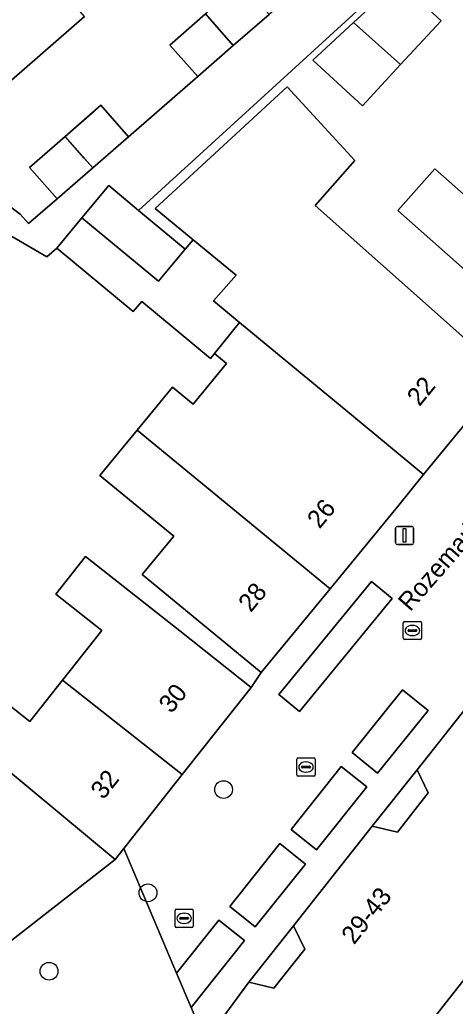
# Model space of a CAD drawing. Extents: x 161881 to 162523, y 381678 to 382381.
# Drawn here: x 162060.4 to 162084.3, y 382033.4 to 382087.6 of the extents above; entities that cross this region are included whole.
import ezdxf

# ---------------------------------------------------------------- set-up
doc = ezdxf.new("R2010")
doc.units = 0
for name, color, linetype in [('IMGEO_Boom', 7, 'Continuous'), ('IMGEO_Erf', 7, 'Continuous'), ('IMGEO_Groenvoorziening', 7, 'Continuous'), ('IMGEO_Kolk', 7, 'Continuous'), ('IMGEO_Lichtmast', 7, 'Continuous'), ('IMGEO_Openbare_ruimte_label', 7, 'Continuous'), ('IMGEO_Pand', 7, 'Continuous'), ('IMGEO_Pand_nummerreeks', 7, 'Continuous'), ('IMGEO_Pand_overbouw', 7, 'Continuous'), ('IMGEO_Pand_vergunning_verleend', 7, 'Continuous'), ('IMGEO_Parkeervlak_open', 7, 'Continuous'), ('IMGEO_Voetpad_open', 7, 'Continuous'), ('IMGEO_Woonerf_open', 7, 'Continuous')]:
    doc.layers.add(name, color=color, linetype=linetype)

msp = doc.modelspace()

# ---------------------------------------------------------------- linework, layer by layer
at = {"layer": 'IMGEO_Boom'}
for centre in [(162071.575, 382045.33), (162067.42, 382039.66), (162061.986, 382035.347)]:
    msp.add_circle(centre, 0.489, dxfattribs=at)
at = {"layer": 'IMGEO_Erf'}
for points in [[(162082.663, 382091.572), (162066.905, 382077.16), (162069.466, 382075.03), (162069.907, 382075.539), (162067.809, 382077.272), (162075.073, 382083.943), (162078.794, 382079.892), (162076.599, 382077.421), (162083.323, 382071.448), (162087.06, 382068.127), (162088.904, 382070.275), (162085.161, 382073.6), (162081.15, 382077.162), (162083.182, 382079.449), (162084.764, 382078.044), (162086.776, 382080.309), (162089.102, 382082.927), (162086.522, 382085.22), (162088.893, 382087.889), (162089.263, 382087.5), (162093.223, 382091.242)], [(162063.941, 382087.819), (162059.914, 382084.317), (162058.933, 382085.442), (162055.177, 382082.169), (162055.093, 382082.095), (162054.473, 382082.858), (162054.137, 382083.272), (162047.556, 382090.818)], [(162046.474, 382089.736), (162054.365, 382081.454), (162060.406, 382076.959), (162060.864, 382076.431), (162062.431, 382077.793), (162060.912, 382079.512), (162062.876, 382081.227), (162064.84, 382082.941), (162066.352, 382081.201), (162070.152, 382084.523), (162068.617, 382086.246), (162070.588, 382087.957)], [(162056.627, 382052.463), (162060.925, 382049.066), (162062.728, 382051.348), (162064.882, 382054.073), (162062.357, 382056.068), (162063.994, 382058.14), (162069.171, 382054.049), (162073.094, 382050.949), (162073.647, 382051.758), (162069.786, 382054.935), (162067.099, 382057.145), (162068.834, 382059.255), (162064.779, 382062.591), (162066.827, 382065.081), (162068.774, 382067.448), (162069.903, 382066.519), (162071.74, 382068.742), (162071.071, 382069.292), (162070.851, 382069.018), (162067.077, 382072.157), (162066.61, 382071.596), (162062.408, 382075.091), (162061.871, 382074.611), (162053.625, 382079.413)]]:
    msp.add_lwpolyline(points, dxfattribs=at)
msp.add_lwpolyline([(162081.303, 382085.172), (162079.207, 382082.908), (162076.484, 382085.416), (162078.71, 382087.476), (162081.182, 382089.764), (162083.536, 382087.585)], close=True, dxfattribs=at)
at = {"layer": 'IMGEO_Groenvoorziening'}
msp.add_lwpolyline([(162075.743, 382049.628), (162080.84, 382055.823), (162079.704, 382056.757), (162074.607, 382050.562)], close=True, dxfattribs=at)
at = {"layer": 'IMGEO_Kolk'}
for p, q in [((162081.447, 382053.644), (162081.447, 382054.496)), ((162081.522, 382054.57), (162082.374, 382054.57)), ((162081.749, 382054.113), (162082.147, 382054.113)), ((162081.935, 382054.35), (162081.96, 382054.35)), ((162082.448, 382054.496), (162082.448, 382053.644)), ((162082.374, 382053.57), (162081.522, 382053.57)), ((162081.706, 382054.064), (162081.706, 382054.076)), ((162082.144, 382054.027), (162081.746, 382054.027)), ((162081.958, 382053.79), (162081.933, 382053.79)), ((162082.19, 382054.076), (162082.19, 382054.064)), ((162075.678, 382047.068), (162076.53, 382047.068)), ((162075.603, 382046.142), (162075.603, 382046.994)), ((162075.862, 382046.562), (162075.862, 382046.574)), ((162076.3, 382046.525), (162075.902, 382046.525)), ((162075.905, 382046.611), (162076.303, 382046.611)), ((162076.091, 382046.848), (162076.116, 382046.848)), ((162076.346, 382046.574), (162076.346, 382046.562)), ((162076.604, 382046.994), (162076.604, 382046.142)), ((162076.53, 382046.068), (162075.678, 382046.068)), ((162076.114, 382046.288), (162076.089, 382046.288)), ((162068.907, 382037.829), (162068.907, 382038.681)), ((162068.982, 382038.755), (162069.834, 382038.755)), ((162069.395, 382038.535), (162069.42, 382038.535)), ((162069.908, 382038.681), (162069.908, 382037.829)), ((162069.166, 382038.249), (162069.166, 382038.261)), ((162069.604, 382038.212), (162069.206, 382038.212)), ((162069.209, 382038.298), (162069.607, 382038.298)), ((162069.418, 382037.975), (162069.393, 382037.975)), ((162069.65, 382038.261), (162069.65, 382038.249)), ((162069.834, 382037.755), (162068.982, 382037.755))]:
    msp.add_line(p, q, dxfattribs=at)
for points in [[(162081.447, 382053.644), (162081.447, 382054.496)], [(162081.522, 382054.57), (162082.374, 382054.57)], [(162082.448, 382054.496), (162082.448, 382053.644)], [(162082.374, 382053.57), (162081.522, 382053.57)], [(162075.678, 382047.068), (162076.53, 382047.068)], [(162075.603, 382046.142), (162075.603, 382046.994)], [(162076.604, 382046.994), (162076.604, 382046.142)], [(162076.53, 382046.068), (162075.678, 382046.068)], [(162068.907, 382037.829), (162068.907, 382038.681)], [(162068.982, 382038.755), (162069.834, 382038.755)], [(162069.908, 382038.681), (162069.908, 382037.829)], [(162069.834, 382037.755), (162068.982, 382037.755)]]:
    msp.add_lwpolyline(points, dxfattribs=at)
for centre, radius, start, end in [((162081.524, 382054.494), 0.0765, 91.552, 178.448), ((162081.524, 382054.494), 0.0765, 91.552, 178.448), ((162081.746, 382054.073), 0.0403, 85.8775, 175.7526), ((162082.151, 382054.075), 0.0386, 1.7309, 96.639), ((162082.372, 382054.494), 0.0765, 1.552, 88.448), ((162082.372, 382054.494), 0.0765, 1.552, 88.448), ((162081.524, 382053.646), 0.0765, 181.552, 268.448), ((162081.524, 382053.646), 0.0765, 181.552, 268.448), ((162081.743, 382054.063), 0.0366, 178.938, 274.7102), ((162082.147, 382054.07), 0.043, 264.8664, 352.4533), ((162082.372, 382053.646), 0.0765, 271.552, 358.448), ((162082.372, 382053.646), 0.0765, 271.552, 358.448), ((162075.68, 382046.992), 0.0765, 91.552, 178.448), ((162075.68, 382046.992), 0.0765, 91.552, 178.448), ((162076.528, 382046.992), 0.0765, 1.552, 88.448), ((162076.528, 382046.992), 0.0765, 1.552, 88.448), ((162075.902, 382046.571), 0.0403, 85.8775, 175.7526), ((162075.899, 382046.561), 0.0366, 178.938, 274.7102), ((162076.303, 382046.568), 0.043, 264.8664, 352.4533), ((162076.307, 382046.573), 0.0386, 1.7309, 96.639), ((162075.68, 382046.144), 0.0765, 181.552, 268.448), ((162075.68, 382046.144), 0.0765, 181.552, 268.448), ((162076.528, 382046.144), 0.0765, 271.552, 358.448), ((162076.528, 382046.144), 0.0765, 271.552, 358.448), ((162068.984, 382038.679), 0.0765, 91.552, 178.448), ((162068.984, 382038.679), 0.0765, 91.552, 178.448), ((162069.832, 382038.679), 0.0765, 1.552, 88.448), ((162069.832, 382038.679), 0.0765, 1.552, 88.448), ((162068.984, 382037.831), 0.0765, 181.552, 268.448), ((162068.984, 382037.831), 0.0765, 181.552, 268.448), ((162069.206, 382038.258), 0.0403, 85.8775, 175.7526), ((162069.203, 382038.248), 0.0366, 178.938, 274.7102), ((162069.607, 382038.255), 0.043, 264.8664, 352.4533), ((162069.611, 382038.26), 0.0386, 1.7309, 96.639), ((162069.832, 382037.831), 0.0765, 271.552, 358.448), ((162069.832, 382037.831), 0.0765, 271.552, 358.448)]:
    msp.add_arc(centre, radius, start, end, dxfattribs=at)
for centre, major_axis, ratio, start_param, end_param in [((162081.934, 382054.07), (-0.387, 0.002), 0.722429, 4.712389, 7.853982), ((162081.959, 382054.07), (-0.39, 0.002), 0.717154, 1.570796, 4.712389), ((162076.09, 382046.568), (-0.387, 0.002), 0.722429, 4.712389, 7.853982), ((162076.115, 382046.568), (-0.39, 0.002), 0.717154, 1.570796, 4.712389), ((162069.394, 382038.255), (-0.387, 0.002), 0.722429, 4.712389, 7.853982), ((162069.419, 382038.255), (-0.39, 0.002), 0.717154, 1.570796, 4.712389)]:
    msp.add_ellipse(centre, major_axis=major_axis, ratio=ratio, start_param=start_param, end_param=end_param, dxfattribs=at)
at = {"layer": 'IMGEO_Lichtmast'}
for p, q in [((162081.023, 382058.897), (162081.023, 382059.697)), ((162081.023, 382059.697), (162081.023, 382058.897)), ((162081.123, 382059.797), (162081.913, 382059.797)), ((162081.913, 382059.797), (162081.123, 382059.797)), ((162082.013, 382059.697), (162082.013, 382058.897)), ((162082.013, 382058.897), (162082.013, 382059.697)), ((162081.913, 382058.797), (162081.123, 382058.797)), ((162081.123, 382058.797), (162081.913, 382058.797))]:
    msp.add_line(p, q, dxfattribs=at)
msp.add_lwpolyline([(162081.443, 382059.672), (162081.593, 382059.672), (162081.593, 382058.922), (162081.443, 382058.922), (162081.443, 382059.672)], dxfattribs=at)
for centre, start, end in [((162081.123, 382059.697), 90, 180), ((162081.123, 382059.697), 90, 180), ((162081.913, 382059.697), 0, 90), ((162081.913, 382059.697), 360, 90), ((162081.123, 382058.897), 180, 270), ((162081.123, 382058.897), 180, 270), ((162081.913, 382058.897), 270, 0), ((162081.913, 382058.897), 270, 0)]:
    msp.add_arc(centre, 0.1, start, end, dxfattribs=at)
at = {"layer": 'IMGEO_Pand'}
for points in [[(162055.4, 382097.641), (162051.36, 382094.127), (162058.933, 382085.442), (162059.914, 382084.317), (162063.941, 382087.819)], [(162072.56, 382089.667), (162070.588, 382087.957), (162072.1, 382086.214), (162074.071, 382087.926)], [(162081.303, 382085.172), (162083.536, 382087.585), (162081.182, 382089.764), (162078.71, 382087.476)], [(162070.588, 382087.957), (162068.617, 382086.246), (162070.152, 382084.523), (162072.1, 382086.214)], [(162081.303, 382085.172), (162078.71, 382087.476), (162076.484, 382085.416), (162079.207, 382082.908)], [(162076.599, 382077.421), (162078.794, 382079.892), (162075.073, 382083.943), (162067.809, 382077.272), (162069.907, 382075.539), (162072.259, 382073.596), (162071.012, 382072.194), (162072.448, 382071.006), (162078.704, 382065.833), (162082.558, 382062.647), (162087.06, 382068.127), (162083.323, 382071.448)], [(162064.84, 382082.941), (162062.876, 382081.227), (162064.388, 382079.494), (162066.352, 382081.201)], [(162064.388, 382079.494), (162062.876, 382081.227), (162060.912, 382079.512), (162062.431, 382077.793)], [(162086.776, 382080.309), (162084.764, 382078.044), (162083.182, 382079.449), (162081.15, 382077.162), (162085.161, 382073.6), (162088.904, 382070.275), (162092.947, 382074.826)], [(162066.905, 382077.16), (162065.264, 382078.525), (162063.784, 382076.746), (162067.999, 382073.266), (162069.466, 382075.03)], [(162063.784, 382076.746), (162062.408, 382075.091), (162066.61, 382071.596), (162067.077, 382072.157), (162070.851, 382069.018), (162071.071, 382069.292), (162072.448, 382071.006), (162071.012, 382072.194), (162072.259, 382073.596), (162069.907, 382075.539), (162069.466, 382075.03), (162067.999, 382073.266)], [(162078.704, 382065.833), (162072.448, 382071.006), (162071.071, 382069.292), (162071.74, 382068.742), (162069.903, 382066.519), (162068.774, 382067.448), (162066.827, 382065.081), (162077.428, 382056.355), (162081.209, 382060.952), (162082.558, 382062.647)], [(162077.428, 382056.355), (162066.827, 382065.081), (162064.779, 382062.591), (162068.834, 382059.255), (162067.099, 382057.145), (162069.786, 382054.935), (162073.647, 382051.758)], [(162062.728, 382051.348), (162069.304, 382046.153), (162073.094, 382050.949), (162069.171, 382054.049), (162063.994, 382058.14), (162062.357, 382056.068), (162064.882, 382054.073)], [(162065.624, 382041.496), (162054.951, 382050.341), (162054.858, 382050.224), (162050.472, 382053.71), (162050.377, 382053.786), (162047.606, 382050.366), (162046.855, 382049.898), (162052.91, 382045.111), (162047.42, 382040.818), (162041.057, 382035.842), (162043.769, 382032.321), (162044.539, 382032.914), (162045.722, 382031.377), (162044.952, 382030.784), (162047.564, 382027.394)], [(162062.728, 382051.348), (162060.925, 382049.066), (162056.627, 382052.463), (162054.951, 382050.341), (162065.624, 382041.496), (162066.089, 382042.085), (162069.304, 382046.153)], [(162081.622, 382028.142), (162080.853, 382029.902), (162091.578, 382043.507), (162089.962, 382044.781), (162090.783, 382045.823), (162089.146, 382047.136), (162085.245, 382050.265), (162082.205, 382046.423), (162082.824, 382045.143), (162081.124, 382042.994), (162079.747, 382043.318), (162075.416, 382037.845), (162076.035, 382036.565), (162074.335, 382034.416), (162072.958, 382034.74), (162070.577, 382031.503), (162073.588, 382024.593)]]:
    msp.add_lwpolyline(points, close=True, dxfattribs=at)
at = {"layer": 'IMGEO_Pand_overbouw'}
for points in [[(162079.747, 382043.318), (162081.124, 382042.994), (162082.824, 382045.143), (162082.205, 382046.423)], [(162075.416, 382037.845), (162072.958, 382034.74), (162074.335, 382034.416), (162076.035, 382036.565)]]:
    msp.add_lwpolyline(points, close=True, dxfattribs=at)
at = {"layer": 'IMGEO_Pand_vergunning_verleend'}
msp.add_lwpolyline([(162063.921, 382080.029), (162062.876, 382081.227), (162064.461, 382082.61), (162064.84, 382082.941), (162066.352, 382081.201), (162064.388, 382079.494)], close=True, dxfattribs=at)
at = {"layer": 'IMGEO_Parkeervlak_open'}
for points in [[(162080.031, 382046.238), (162082.806, 382049.684), (162081.399, 382050.806), (162078.633, 382047.36)], [(162103.972, 382038.147), (162093.049, 382049.003), (162092.8, 382048.653), (162090.783, 382045.823), (162089.962, 382044.781), (162091.578, 382043.507), (162080.853, 382029.902), (162081.622, 382028.142), (162086.603, 382030.317), (162086.925, 382029.58), (162089.255, 382030.597), (162091.585, 382031.615), (162094.084, 382032.706), (162096.583, 382033.797), (162099.082, 382034.888), (162101.589, 382035.982), (162102.186, 382036.243)], [(162079.441, 382045.475), (162078.037, 382046.607), (162075.285, 382043.128), (162076.68, 382042.013)], [(162076.074, 382041.241), (162074.663, 382042.368), (162071.919, 382038.914), (162073.317, 382037.797)], [(162068.992, 382035.24), (162069.789, 382033.361), (162072.716, 382037.039), (162071.32, 382038.151)]]:
    msp.add_lwpolyline(points, close=True, dxfattribs=at)
at = {"layer": 'IMGEO_Voetpad_open'}
for points in [[(162054.365, 382081.454), (162046.474, 382089.736), (162045.016, 382091.412), (162043.519, 382090.148), (162053.625, 382079.413), (162061.871, 382074.611), (162062.408, 382075.091), (162063.784, 382076.746), (162065.264, 382078.525), (162066.905, 382077.16), (162082.663, 382091.572), (162081.119, 382093.259), (162080.249, 382093.335), (162079.764, 382092.912), (162077.765, 382091.172), (162074.071, 382087.926), (162072.1, 382086.214), (162070.152, 382084.523), (162066.352, 382081.201), (162064.388, 382079.494), (162062.431, 382077.793), (162060.864, 382076.431), (162060.406, 382076.959)], [(162079.747, 382043.318), (162081.124, 382042.994), (162082.824, 382045.143), (162082.205, 382046.423)], [(162069.789, 382033.361), (162068.992, 382035.24), (162066.089, 382042.085), (162065.624, 382041.496), (162047.564, 382027.394), (162045.217, 382025.401), (162049.849, 382019.352), (162053.833, 382013.795), (162057.352, 382008.476), (162058.902, 382005.997), (162062.291, 382006.229), (162060.888, 382009.538), (162061.341, 382010.107), (162070.724, 382021.65), (162076.855, 382007.857), (162077.174, 382007.14), (162081.094, 382007.361), (162078.98, 382012.213), (162076.155, 382018.699), (162073.588, 382024.593), (162070.577, 382031.503)], [(162072.958, 382034.74), (162074.335, 382034.416), (162076.035, 382036.565), (162075.416, 382037.845)]]:
    msp.add_lwpolyline(points, close=True, dxfattribs=at)
at = {"layer": 'IMGEO_Woonerf_open'}
msp.add_lwpolyline([(162087.06, 382068.127), (162082.558, 382062.647), (162081.209, 382060.952), (162077.428, 382056.355), (162073.647, 382051.758), (162073.094, 382050.949), (162069.304, 382046.153), (162066.089, 382042.085), (162068.992, 382035.24), (162071.32, 382038.151), (162072.716, 382037.039), (162069.789, 382033.361), (162070.577, 382031.503), (162072.958, 382034.74), (162075.416, 382037.845), (162079.747, 382043.318), (162082.205, 382046.423), (162085.245, 382050.265)], dxfattribs=at)
for points in [[(162075.743, 382049.628), (162074.607, 382050.562), (162079.704, 382056.757), (162080.84, 382055.823)], [(162080.031, 382046.238), (162078.633, 382047.36), (162081.399, 382050.806), (162082.806, 382049.684)], [(162079.441, 382045.475), (162076.68, 382042.013), (162075.285, 382043.128), (162078.037, 382046.607)], [(162076.074, 382041.241), (162073.317, 382037.797), (162071.919, 382038.914), (162074.663, 382042.368)]]:
    msp.add_lwpolyline(points, close=True, dxfattribs=at)

# ---------------------------------------------------------------- texts
at = {"layer": 'IMGEO_Openbare_ruimte_label'}
msp.add_text('Rozemarijnstraat', height=1, rotation=48.771, dxfattribs=at).set_placement((162081.822, 382055.072))
at = {"layer": 'IMGEO_Pand_nummerreeks'}
for s, rotation, p in [('22', 50.5979, (162082.335, 382066.346)), ('26', 50.5635, (162076.848, 382059.617)), ('28', 50.5629, (162073.069, 382055.022)), ('30', 51.6825, (162068.712, 382049.468)), ('32', 51.6977, (162064.973, 382044.735)), ('29-43', 51.5688, (162078.745, 382036.766))]:
    msp.add_text(s, height=1, rotation=rotation, dxfattribs=at).set_placement(p)

doc.saveas('drawing.dxf')
